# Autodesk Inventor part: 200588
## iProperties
Created: 2007-10
Part Number: 200588
Document SubType Name: Modeling
Designer: TH
Density: 7.85 g/cm^3
Mass: 178.858 g
Surface Area: 163.354 cm^2
Volume: 22.7845 cm^3
Material: Steel
Description: BALL SCREW BRACKET
Component Category: Lower Component
Author: TH
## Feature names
1. Extrusion1
2. Extrusion2
3. Fillet1
4. Extrusion3
